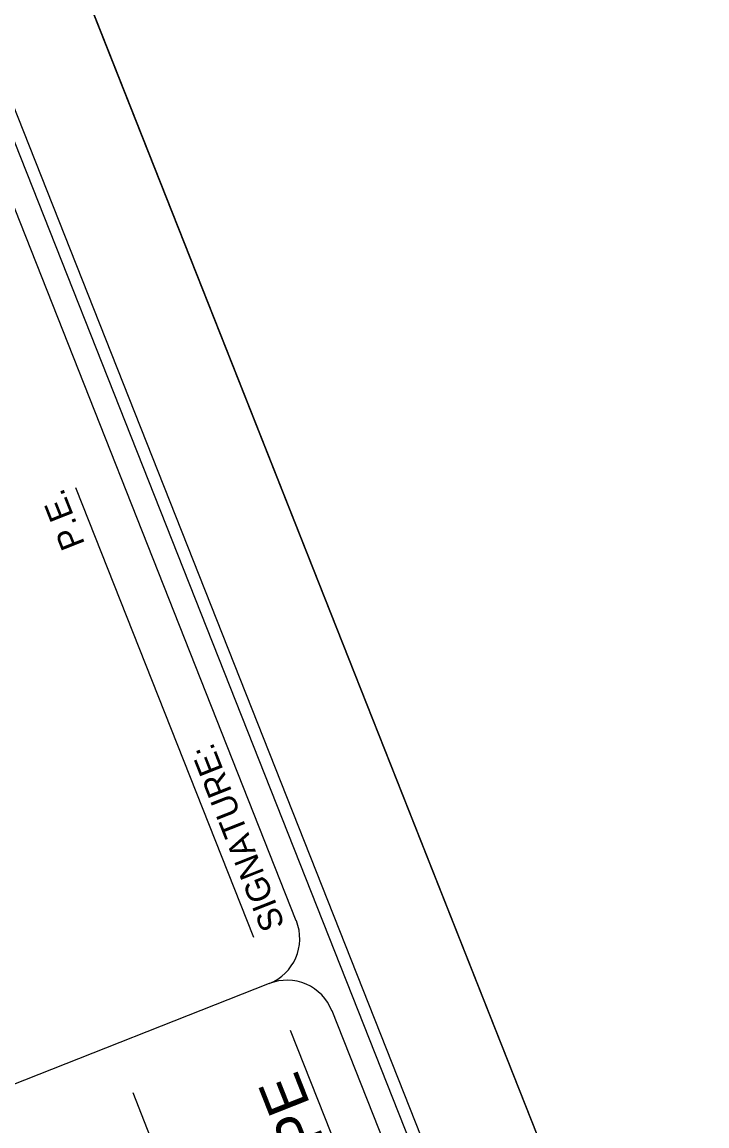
# Model space of a CAD drawing. Extents: x 1247235 to 1260080, y 742320 to 754020.
# Drawn here: x 1252131 to 1252768, y 749890 to 750916 of the extents above; entities that cross this region are included whole.
import ezdxf

# ---------------------------------------------------------------- set-up
doc = ezdxf.new("R2010")
doc.units = 0
for name, color, linetype in [('Sheet Cutting Line CELL', 7, 'Continuous'), ('Sheet Data Field CELL', 7, 'Continuous'), ('Sheet Plot Border Inside CELL', 7, 'Continuous'), ('Sheet Plot Border Outside CELL', 7, 'Continuous'), ('Sheet Title CELL', 7, 'Continuous')]:
    doc.layers.add(name, color=color, linetype=linetype)

msp = doc.modelspace()

# ---------------------------------------------------------------- linework, layer by layer
at = {"layer": 'Sheet Cutting Line CELL'}
msp.add_line((1254624.4, 744786.1), (1251837.9, 751833.2), dxfattribs=at)
at = {"layer": 'Sheet Plot Border Inside CELL'}
msp.add_lwpolyline([(1254509, 744803.4), (1251751.5, 751777.2), (1247336.2, 750031.4), (1250093.7, 743057.5)], close=True, dxfattribs=at)
at = {"layer": 'Sheet Plot Border Outside CELL'}
msp.add_lwpolyline([(1247234.8, 750013.1), (1250021.3, 742966), (1254624.4, 744786.1), (1251837.9, 751833.2)], close=True, dxfattribs=at)
at = {"layer": 'Sheet Title CELL'}
for p, q in [((1252346.3, 750064.7), (1252180.9, 750483.2)), ((1252360.5, 750022), (1251691, 749757.2)), ((1252639, 749324.4), (1252380.5, 749978.3)), ((1252492.5, 749266.5), (1252234, 749920.4))]:
    msp.add_line(p, q, dxfattribs=at)
for points in [[(1254227, 745485.4), (1251778, 751678.9)], [(1252385.8, 750080.4), (1252055.3, 750916.3)], [(1252890.5, 748804), (1252419, 749996.7)]]:
    msp.add_lwpolyline(points, dxfattribs=at)
for centre, start, end in [((1252344, 750063.8), 291.5743, 21.5743), ((1252377.1, 749980.1), 21.5718, 111.5743)]:
    msp.add_arc(centre, 45, start, end, dxfattribs=at)

# ---------------------------------------------------------------- texts
at = {"layer": 'Sheet Data Field CELL'}
for s, p in [('OLIVIA PILKINGTON, PE', (1252607.8, 749381.7)), ('CHRISTOPHER K. HAIRE, PE', (1252377.6, 749254.9))]:
    msp.add_text(s, height=39.375, rotation=111.5743, dxfattribs=at).set_placement(p)
at = {"layer": 'Sheet Title CELL'}
for s, p in [('P.E.', (1252189.5, 750430.9)), ('SIGNATURE:', (1252375.4, 750076.2))]:
    msp.add_text(s, height=22.5, rotation=111.5743, dxfattribs=at).set_placement(p)

doc.saveas('drawing.dxf')
